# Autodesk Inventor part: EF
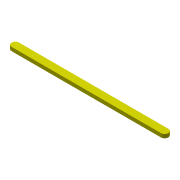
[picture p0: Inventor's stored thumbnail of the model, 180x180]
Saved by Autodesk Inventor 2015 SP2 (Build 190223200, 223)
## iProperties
Created: 2019-08
Part Number: EF
Material: 一般
Document SubType Name: Modeling
Designer: Kuan_Lun Hsu
Density: 1 g/cm^3
Appearance: Smooth - Yellow
Mass: 0.43927 g
Surface Area: 6.30686 cm^2
Volume: 0.43927 cm^3
Author: Kuan_Lun Hsu
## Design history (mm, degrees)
sketch "草圖1"
  geometry: L1 (0, 0)-(40, 0); L2 (0, -2.5)-(40, -2.5); L3 (40, 2.5)-(0, 2.5); A1 r 2.5 centre (0, 0) between (0, 2.5) and (0, -2.5); A2 r 2.5 centre (40, 0) between (40, -2.5) and (40, 2.5); 1 further point
  constraints: 8 end point, 4 point on circle, 4 tangent, 2 centre point, 1 horizontal, 1 midpoint, 1 parallel
  dimensions: "d0" = 40 distance of L1.start L1.end (= EF_); "d1" = 5 distance between parallel lines of L2 L3 (= w_)
extrude "擠出1" new body sketch "草圖1" distance "d2" = 2 (= t_); taper "d3" = 0 deg
node "實體1"
other parameters: "EF_" = 40 [user parameter; used in 1 equation term], "w_" = 5 [user parameter; used in 1 equation term], "t_" = 2 [user parameter; used in 1 equation term]
